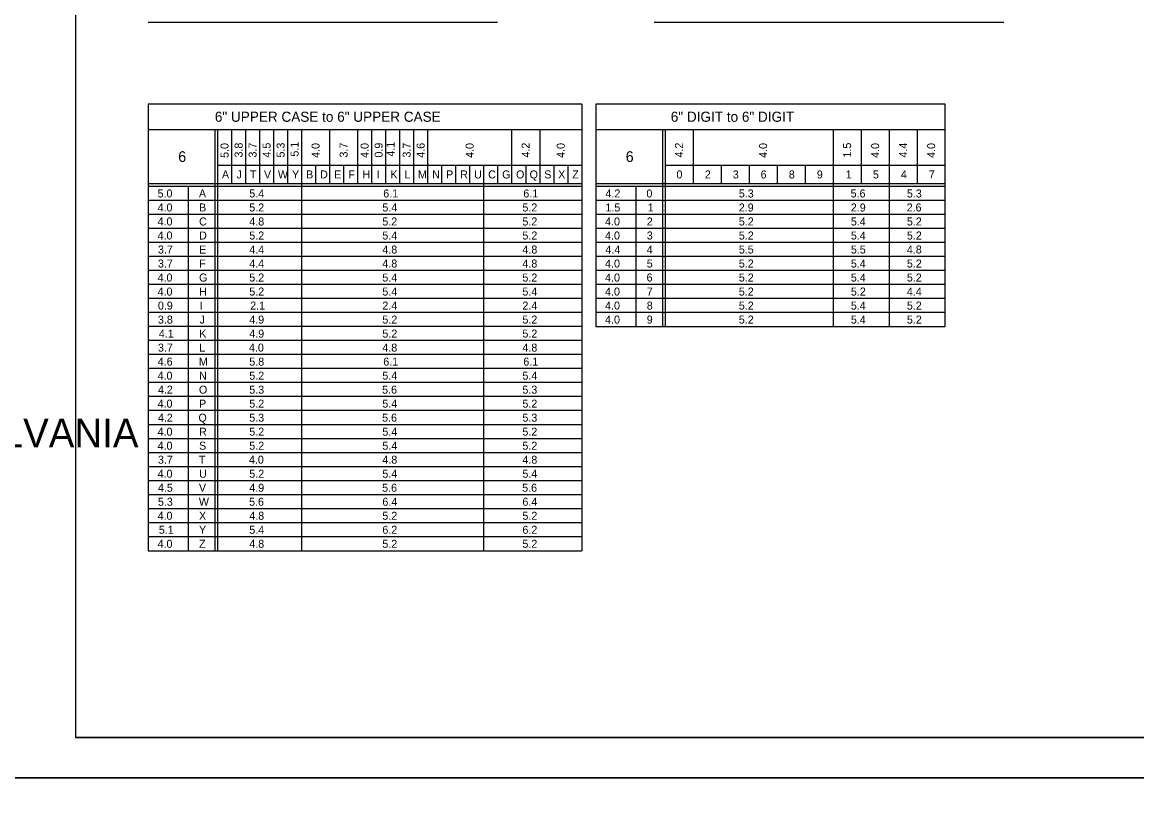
# Model space of a CAD drawing. Extents: x 638421 to 641849, y 297270 to 299646.
# Drawn here: x 640123.3 to 640541.1, y 297856.1 to 298146.6 of the extents above; entities that cross this region are included whole.
import ezdxf

# ---------------------------------------------------------------- set-up
doc = ezdxf.new("R2010")
doc.units = 0
for name, color, linetype in [('1', 7, 'Continuous'), ('2', 7, 'Continuous'), ('XCS-GRID-HVGL', 7, 'Continuous')]:
    doc.layers.add(name, color=color, linetype=linetype)

msp = doc.modelspace()

# ---------------------------------------------------------------- linework, layer by layer
at = {"layer": '1'}
for p, q in [((640143.31, 298442.63), (640143.31, 297878.63)), ((640929.31, 297878.63), (640143.31, 297878.63)), ((640143.31, 297878.63), (640729.31, 297878.63))]:
    msp.add_line(p, q, dxfattribs=at)
at = {"layer": '2'}
for p, q in [((640170.51, 298146.63), (640301.51, 298146.63)), ((640360.21, 298146.63), (640491.21, 298146.63)), ((640333.01, 298116), (640170.51, 298116)), ((640170.51, 298116), (640170.51, 297948.63)), ((640333.01, 298116), (640333.01, 297948.63)), ((640469.26, 298116), (640338.26, 298116)), ((640338.26, 298116), (640338.26, 298032.63)), ((640469.26, 298032.63), (640469.26, 298116)), ((640170.51, 298106.5), (640333.01, 298106.5)), ((640195.51, 298106.5), (640195.51, 297948.63)), ((640196.51, 298106.5), (640196.51, 297948.63)), ((640201.76, 298106.5), (640201.76, 298086.13)), ((640207.01, 298106.5), (640207.01, 298086.13)), ((640212.26, 298106.5), (640212.26, 298086.13)), ((640217.51, 298106.5), (640217.51, 298086.13)), ((640222.76, 298106.5), (640222.76, 298086.13)), ((640228.01, 298106.5), (640228.01, 297948.63)), ((640238.51, 298106.5), (640238.51, 298086.13)), ((640249.01, 298106.5), (640249.01, 298086.13)), ((640254.26, 298106.5), (640254.26, 298086.13)), ((640259.51, 298106.5), (640259.51, 298086.13)), ((640264.76, 298106.5), (640264.76, 298086.13)), ((640270.01, 298106.5), (640270.01, 298086.13)), ((640275.26, 298106.5), (640275.26, 298086.13)), ((640306.76, 298106.5), (640306.76, 298086.13)), ((640317.26, 298106.5), (640317.26, 298086.13)), ((640338.26, 298106.5), (640469.26, 298106.5)), ((640363.26, 298106.5), (640363.26, 298032.63)), ((640364.26, 298106.5), (640364.26, 298032.63)), ((640374.76, 298106.5), (640374.76, 298086.13)), ((640427.26, 298106.5), (640427.26, 298032.63)), ((640437.76, 298106.5), (640437.76, 298086.13)), ((640448.26, 298106.5), (640448.26, 298032.63)), ((640458.76, 298106.5), (640458.76, 298086.13)), ((640196.51, 298093.13), (640333.01, 298093.13)), ((640233.26, 298093.13), (640233.26, 298086.13)), ((640243.76, 298093.13), (640243.76, 298086.13)), ((640280.51, 298093.13), (640280.51, 298086.13)), ((640285.76, 298093.13), (640285.76, 298086.13)), ((640291.01, 298093.13), (640291.01, 298086.13)), ((640291.01, 298093.13), (640291.01, 298086.13)), ((640296.26, 298093.13), (640296.26, 297948.63)), ((640301.51, 298093.13), (640301.51, 298086.13)), ((640312.01, 298093.13), (640312.01, 298086.13)), ((640322.51, 298093.13), (640322.51, 298086.13)), ((640327.76, 298093.13), (640327.76, 298086.13)), ((640364.26, 298093.13), (640469.26, 298093.13)), ((640385.26, 298093.13), (640385.26, 298086.13)), ((640395.76, 298093.13), (640395.76, 298086.13)), ((640406.26, 298093.13), (640406.26, 298086.13)), ((640416.76, 298093.13), (640416.76, 298086.13)), ((640333.01, 298086.13), (640170.51, 298086.13)), ((640333.01, 298085.13), (640170.51, 298085.13)), ((640185.51, 298085.13), (640185.51, 297948.63)), ((640469.26, 298086.13), (640338.26, 298086.13)), ((640469.26, 298085.13), (640338.26, 298085.13)), ((640353.26, 298085.13), (640353.26, 298032.63)), ((640333.01, 298079.88), (640170.51, 298079.88)), ((640469.26, 298079.88), (640338.26, 298079.88)), ((640333.01, 298074.63), (640170.51, 298074.63)), ((640469.26, 298074.63), (640338.26, 298074.63)), ((640333.01, 298069.38), (640170.51, 298069.38)), ((640469.26, 298069.38), (640338.26, 298069.38)), ((640333.01, 298064.13), (640170.51, 298064.13)), ((640469.26, 298064.13), (640338.26, 298064.13)), ((640333.01, 298058.88), (640170.51, 298058.88)), ((640469.26, 298058.88), (640338.26, 298058.88)), ((640333.01, 298053.63), (640170.51, 298053.63)), ((640469.26, 298053.63), (640338.26, 298053.63)), ((640333.01, 298048.38), (640170.51, 298048.38)), ((640469.26, 298048.38), (640338.26, 298048.38)), ((640333.01, 298043.13), (640170.51, 298043.13)), ((640469.26, 298043.13), (640338.26, 298043.13)), ((640333.01, 298037.88), (640170.51, 298037.88)), ((640469.26, 298037.88), (640338.26, 298037.88)), ((640333.01, 298032.63), (640170.51, 298032.63)), ((640338.26, 298032.63), (640469.26, 298032.63)), ((640333.01, 298027.38), (640170.51, 298027.38)), ((640333.01, 298022.13), (640170.51, 298022.13)), ((640333.01, 298016.88), (640170.51, 298016.88)), ((640333.01, 298011.63), (640170.51, 298011.63)), ((640333.01, 298006.38), (640170.51, 298006.38)), ((640333.01, 298001.13), (640170.51, 298001.13)), ((640333.01, 297995.88), (640170.51, 297995.88)), ((640333.01, 297990.63), (640170.51, 297990.63)), ((640333.01, 297985.38), (640170.51, 297985.38)), ((640333.01, 297980.13), (640170.51, 297980.13)), ((640333.01, 297974.88), (640170.51, 297974.88)), ((640333.01, 297969.63), (640170.51, 297969.63)), ((640333.01, 297964.38), (640170.51, 297964.38)), ((640333.01, 297959.13), (640170.51, 297959.13)), ((640333.01, 297953.88), (640170.51, 297953.88)), ((640170.51, 297948.63), (640170.51, 297948.63)), ((640170.51, 297948.63), (640333.01, 297948.63))]:
    msp.add_line(p, q, dxfattribs=at)
at = {"layer": 'XCS-GRID-HVGL'}
for points in [[(640103.31, 298457.63), (640944.31, 298457.63), (640944.31, 297863.63), (640103.31, 297863.63)], [(640103.31, 297863.63), (640944.31, 297863.63), (640944.31, 297269.63), (640103.31, 297269.63)]]:
    msp.add_lwpolyline(points, close=True, dxfattribs=at)

# ---------------------------------------------------------------- texts
at = {"layer": '1'}
msp.add_text('COMMONWEALTH OF PENNSYLVANIA', height=10.7828, dxfattribs=at).set_placement((639900.9, 297987.36))
at = {"layer": '2'}
for s, height, p in [('6" UPPER CASE to 6" UPPER CASE', 3.8, (640195.5, 298109.35)), ('6" DIGIT to 6" DIGIT', 3.8, (640366.41, 298109.35)), ('6', 4, (640181.77, 298094.31)), ('6', 4, (640349.52, 298094.31)), ('A', 3, (640198.16, 298088.13)), ('J', 3, (640203.64, 298088.13)), ('T', 3, (640208.64, 298088.13)), ('V', 3, (640213.91, 298088.13)), ('W', 3, (640219.13, 298088.13)), ('Y', 3, (640224.44, 298088.13)), ('B', 3, (640229.7, 298088.13)), ('D', 3, (640234.95, 298088.13)), ('E', 3, (640240.22, 298088.13)), ('F', 3, (640245.52, 298088.13)), ('H', 3, (640250.79, 298088.13)), ('I', 3, (640256.2, 298088.13)), ('K', 3, (640261.29, 298088.13)), ('L', 3, (640266.54, 298088.13)), ('M', 3, (640271.63, 298088.13)), ('N', 3, (640276.95, 298088.13)), ('P', 3, (640282.2, 298088.13)), ('R', 3, (640287.45, 298088.13)), ('U', 3, (640292.69, 298088.13)), ('C', 3, (640297.95, 298088.13)), ('G', 3, (640303.2, 298088.13)), ('O', 3, (640308.41, 298088.13)), ('Q', 3, (640313.48, 298088.13)), ('S', 3, (640318.97, 298088.13)), ('X', 3, (640324.19, 298088.13)), ('Z', 3, (640329.45, 298088.13)), ('0', 3, (640368.53, 298088.13)), ('2', 3, (640379.16, 298088.13)), ('3', 3, (640389.66, 298088.13)), ('6', 3, (640400.08, 298088.13)), ('8', 3, (640410.66, 298088.13)), ('9', 3, (640421.15, 298088.13)), ('1', 3, (640432, 298088.13)), ('5', 3, (640442.16, 298088.13)), ('4', 3, (640452.66, 298088.13)), ('7', 3, (640463.16, 298088.13)), ('5.0', 3, (640174.03, 298081)), ('A', 3, (640189.53, 298081)), ('5.4', 3, (640208.41, 298081)), ('6.1', 3, (640258.63, 298081)), ('6.1', 3, (640311.13, 298081)), ('4.2', 3, (640341.91, 298081)), ('0', 3, (640357.28, 298081)), ('5.3', 3, (640391.91, 298081)), ('5.6', 3, (640433.83, 298081)), ('5.3', 3, (640454.91, 298081)), ('4.0', 3, (640174.03, 298075.75)), ('B', 3, (640189.58, 298075.75)), ('5.2', 3, (640208.41, 298075.75)), ('5.4', 3, (640258.29, 298075.75)), ('5.2', 3, (640310.79, 298075.75)), ('1.5', 3, (640341.91, 298075.75)), ('1', 3, (640357.75, 298075.75)), ('2.9', 3, (640391.9, 298075.75)), ('2.9', 3, (640433.9, 298075.75)), ('2.6', 3, (640454.83, 298075.75)), ('4.0', 3, (640174.03, 298070.5)), ('C', 3, (640189.58, 298070.5)), ('4.8', 3, (640208.41, 298070.5)), ('5.2', 3, (640258.29, 298070.5)), ('5.2', 3, (640310.79, 298070.5)), ('4.0', 3, (640341.78, 298070.5)), ('2', 3, (640357.41, 298070.5)), ('5.2', 3, (640391.91, 298070.5)), ('5.4', 3, (640433.91, 298070.5)), ('5.2', 3, (640454.91, 298070.5)), ('4.0', 3, (640174.03, 298065.25)), ('D', 3, (640189.58, 298065.25)), ('5.2', 3, (640208.41, 298065.25)), ('5.4', 3, (640258.29, 298065.25)), ('5.2', 3, (640310.79, 298065.25)), ('4.0', 3, (640341.78, 298065.25)), ('3', 3, (640357.41, 298065.25)), ('5.2', 3, (640391.91, 298065.25)), ('5.4', 3, (640433.91, 298065.25)), ('5.2', 3, (640454.91, 298065.25)), ('3.7', 3, (640174.16, 298060)), ('E', 3, (640189.59, 298060)), ('4.4', 3, (640208.41, 298060)), ('4.8', 3, (640258.29, 298060)), ('4.8', 3, (640310.79, 298060)), ('4.4', 3, (640341.91, 298060)), ('4', 3, (640357.41, 298060)), ('5.5', 3, (640391.91, 298060)), ('5.5', 3, (640433.91, 298060)), ('4.8', 3, (640454.91, 298060)), ('3.7', 3, (640174.16, 298054.75)), ('F', 3, (640189.65, 298054.75)), ('4.4', 3, (640208.41, 298054.75)), ('4.8', 3, (640258.29, 298054.75)), ('4.8', 3, (640310.79, 298054.75)), ('4.0', 3, (640341.78, 298054.75)), ('5', 3, (640357.41, 298054.75)), ('5.2', 3, (640391.91, 298054.75)), ('5.4', 3, (640433.91, 298054.75)), ('5.2', 3, (640454.91, 298054.75)), ('4.0', 3, (640174.03, 298049.5)), ('G', 3, (640189.58, 298049.5)), ('5.2', 3, (640208.41, 298049.5)), ('5.4', 3, (640258.29, 298049.5)), ('5.2', 3, (640310.79, 298049.5)), ('4.0', 3, (640341.78, 298049.5)), ('6', 3, (640357.33, 298049.5)), ('5.2', 3, (640391.91, 298049.5)), ('5.4', 3, (640433.91, 298049.5)), ('5.2', 3, (640454.91, 298049.5)), ('4.0', 3, (640174.03, 298044.25)), ('H', 3, (640189.66, 298044.25)), ('5.2', 3, (640208.41, 298044.25)), ('5.4', 3, (640258.29, 298044.25)), ('5.4', 3, (640310.79, 298044.25)), ('4.0', 3, (640341.78, 298044.25)), ('7', 3, (640357.41, 298044.25)), ('5.2', 3, (640391.91, 298044.25)), ('5.2', 3, (640433.91, 298044.25)), ('4.4', 3, (640454.91, 298044.25)), ('0.9', 3, (640174.15, 298039)), ('I', 3, (640189.83, 298039)), ('2.1', 3, (640208.75, 298039)), ('2.4', 3, (640258.29, 298039)), ('2.4', 3, (640310.79, 298039)), ('4.0', 3, (640341.78, 298039)), ('8', 3, (640357.41, 298039)), ('5.2', 3, (640391.91, 298039)), ('5.4', 3, (640433.91, 298039)), ('5.2', 3, (640454.91, 298039)), ('3.8', 3, (640174.16, 298033.75)), ('J', 3, (640189.77, 298033.75)), ('4.9', 3, (640208.4, 298033.75)), ('5.2', 3, (640258.29, 298033.75)), ('5.2', 3, (640310.79, 298033.75)), ('4.0', 3, (640341.78, 298033.75)), ('9', 3, (640357.4, 298033.75)), ('5.2', 3, (640391.91, 298033.75)), ('5.4', 3, (640433.91, 298033.75)), ('5.2', 3, (640454.91, 298033.75)), ('4.1', 3, (640174.5, 298028.5)), ('K', 3, (640189.66, 298028.5)), ('4.9', 3, (640208.4, 298028.5)), ('5.2', 3, (640258.29, 298028.5)), ('5.2', 3, (640310.79, 298028.5)), ('3.7', 3, (640174.16, 298023.25)), ('L', 3, (640189.66, 298023.25)), ('4.0', 3, (640208.28, 298023.25)), ('4.8', 3, (640258.29, 298023.25)), ('4.8', 3, (640310.79, 298023.25)), ('4.6', 3, (640174.08, 298018)), ('M', 3, (640189.51, 298018)), ('5.8', 3, (640208.41, 298018)), ('6.1', 3, (640258.63, 298018)), ('6.1', 3, (640311.13, 298018)), ('4.0', 3, (640174.03, 298012.75)), ('N', 3, (640189.58, 298012.75)), ('5.2', 3, (640208.41, 298012.75)), ('5.4', 3, (640258.29, 298012.75)), ('5.4', 3, (640310.79, 298012.75)), ('4.2', 3, (640174.16, 298007.5)), ('O', 3, (640189.53, 298007.5)), ('5.3', 3, (640208.41, 298007.5)), ('5.6', 3, (640258.2, 298007.5)), ('5.3', 3, (640310.79, 298007.5)), ('4.0', 3, (640174.03, 298002.25)), ('P', 3, (640189.58, 298002.25)), ('5.2', 3, (640208.41, 298002.25)), ('5.4', 3, (640258.29, 298002.25)), ('5.2', 3, (640310.79, 298002.25)), ('4.2', 3, (640174.16, 297997)), ('Q', 3, (640189.35, 297997)), ('5.3', 3, (640208.41, 297997)), ('5.6', 3, (640258.2, 297997)), ('5.3', 3, (640310.79, 297997)), ('4.0', 3, (640174.03, 297991.75)), ('R', 3, (640189.58, 297991.75)), ('5.2', 3, (640208.41, 297991.75)), ('5.4', 3, (640258.29, 297991.75)), ('5.2', 3, (640310.79, 297991.75)), ('4.0', 3, (640174.03, 297986.5)), ('S', 3, (640189.59, 297986.5)), ('5.2', 3, (640208.41, 297986.5)), ('5.4', 3, (640258.29, 297986.5)), ('5.2', 3, (640310.79, 297986.5)), ('3.7', 3, (640174.16, 297981.25)), ('4.0', 3, (640208.28, 297981.25)), ('4.8', 3, (640258.29, 297981.25)), ('4.8', 3, (640310.79, 297981.25)), ('T', 3, (640189.52, 297981.25)), ('4.0', 3, (640174.03, 297976)), ('U', 3, (640189.57, 297976)), ('5.2', 3, (640208.41, 297976)), ('5.4', 3, (640258.29, 297976)), ('5.4', 3, (640310.79, 297976)), ('4.5', 3, (640174.16, 297970.75)), ('V', 3, (640189.53, 297970.75)), ('4.9', 3, (640208.4, 297970.75)), ('5.6', 3, (640258.2, 297970.75)), ('5.6', 3, (640310.7, 297970.75)), ('5.3', 3, (640174.16, 297965.5)), ('W', 3, (640189.51, 297965.5)), ('5.6', 3, (640208.33, 297965.5)), ('6.4', 3, (640258.29, 297965.5)), ('6.4', 3, (640310.79, 297965.5)), ('4.0', 3, (640174.03, 297960.25)), ('X', 3, (640189.57, 297960.25)), ('4.8', 3, (640208.41, 297960.25)), ('5.2', 3, (640258.29, 297960.25)), ('5.2', 3, (640310.79, 297960.25)), ('5.1', 3, (640174.5, 297955)), ('Y', 3, (640189.57, 297955)), ('5.4', 3, (640208.41, 297955)), ('6.2', 3, (640258.29, 297955)), ('6.2', 3, (640310.79, 297955)), ('4.0', 3, (640174.03, 297949.75)), ('Z', 3, (640189.58, 297949.75)), ('4.8', 3, (640208.41, 297949.75)), ('5.2', 3, (640258.29, 297949.75)), ('5.2', 3, (640310.79, 297949.75))]:
    msp.add_text(s, height=height, dxfattribs=at).set_placement(p)
for s, p in [('3.8', (640205.89, 298095.96)), ('3.7', (640211.14, 298095.96)), ('4.5', (640216.39, 298095.96)), ('5.3', (640221.64, 298095.96)), ('5.1', (640226.89, 298096.31)), ('3.7', (640245.26, 298095.96)), ('0.9', (640258.39, 298095.95)), ('4.1', (640262.87, 298096.31)), ('3.7', (640268.89, 298095.96)), ('4.6', (640274.14, 298095.88)), ('4.2', (640313.51, 298095.96)), ('4.2', (640371.01, 298095.96)), ('1.5', (640434.01, 298095.96)), ('4.4', (640455.01, 298095.96)), ('5.0', (640200.64, 298095.83)), ('4.0', (640234.76, 298095.83)), ('4.0', (640253.14, 298095.83)), ('4.0', (640292.51, 298095.83)), ('4.0', (640326.64, 298095.83)), ('4.0', (640402.51, 298095.83)), ('4.0', (640444.51, 298095.83)), ('4.0', (640465.51, 298095.83))]:
    msp.add_text(s, height=3, rotation=90, dxfattribs=at).set_placement(p)

doc.saveas('drawing.dxf')
